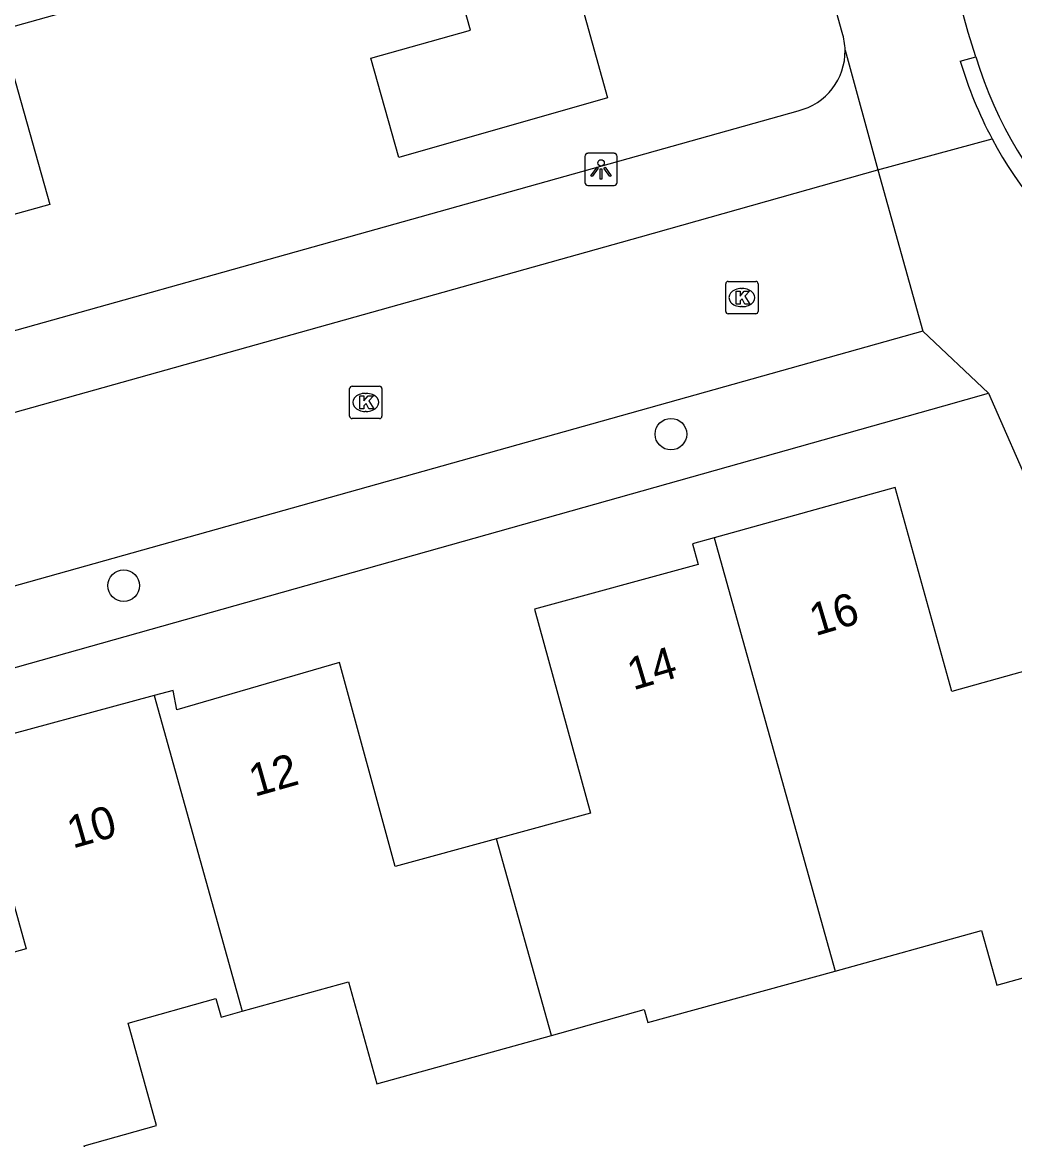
# Model space of a CAD drawing. Extents: x 159628 to 160723, y 388176 to 389416.
# Drawn here: x 160120.05 to 160150.76, y 388377.97 to 388412.56 of the extents above; entities that cross this region are included whole.
import ezdxf

# ---------------------------------------------------------------- set-up
doc = ezdxf.new("R2010")
doc.units = 0
for name, color, linetype in [('IMGEO_Boom', 7, 'Continuous'), ('IMGEO_Kolk', 7, 'Continuous'), ('IMGEO_Lichtpunt', 7, 'Continuous'), ('IMGEO_Pand', 7, 'Continuous'), ('IMGEO_Pand_nummerreeks', 7, 'Continuous'), ('IMGEO_Rijbaan_lokaal_open', 7, 'Continuous'), ('IMGEO_Voetpad_open', 7, 'Continuous')]:
    doc.layers.add(name, color=color, linetype=linetype)

msp = doc.modelspace()

# ---------------------------------------------------------------- linework, layer by layer
at = {"layer": 'IMGEO_Boom'}
for centre in [(160140.122, 388399.811), (160123.188, 388395.123)]:
    msp.add_circle(centre, 0.489, dxfattribs=at)
at = {"layer": 'IMGEO_Kolk'}
for p, q in [((160141.819, 388403.612), (160141.819, 388404.464)), ((160141.894, 388404.538), (160142.746, 388404.538)), ((160142.82, 388404.464), (160142.82, 388403.612)), ((160142.307, 388404.318), (160142.332, 388404.318)), ((160142.33, 388403.758), (160142.305, 388403.758)), ((160142.746, 388403.538), (160141.894, 388403.538)), ((160130.179, 388400.368), (160130.179, 388401.22)), ((160130.254, 388401.294), (160131.106, 388401.294)), ((160130.667, 388401.074), (160130.692, 388401.074)), ((160131.18, 388401.22), (160131.18, 388400.368)), ((160131.106, 388400.294), (160130.254, 388400.294)), ((160130.69, 388400.514), (160130.665, 388400.514))]:
    msp.add_line(p, q, dxfattribs=at)
for points in [[(160141.819, 388403.612), (160141.819, 388404.464)], [(160141.894, 388404.538), (160142.746, 388404.538)], [(160142.82, 388404.464), (160142.82, 388403.612)], [(160142.14, 388404.238), (160142.263, 388404.238), (160142.263, 388404.087), (160142.393, 388404.238), (160142.557, 388404.238), (160142.411, 388404.087), (160142.564, 388403.838), (160142.412, 388403.838), (160142.327, 388404.002), (160142.263, 388403.935), (160142.263, 388403.838), (160142.14, 388403.838), (160142.14, 388404.238)], [(160142.746, 388403.538), (160141.894, 388403.538)], [(160130.179, 388400.368), (160130.179, 388401.22)], [(160130.254, 388401.294), (160131.106, 388401.294)], [(160130.5, 388400.994), (160130.623, 388400.994), (160130.623, 388400.843), (160130.753, 388400.994), (160130.917, 388400.994), (160130.771, 388400.843), (160130.924, 388400.594), (160130.772, 388400.594), (160130.687, 388400.758), (160130.623, 388400.691), (160130.623, 388400.594), (160130.5, 388400.594), (160130.5, 388400.994)], [(160131.18, 388401.22), (160131.18, 388400.368)], [(160131.106, 388400.294), (160130.254, 388400.294)]]:
    msp.add_lwpolyline(points, dxfattribs=at)
for centre, start, end in [((160141.896, 388404.462), 91.552, 178.448), ((160141.896, 388404.462), 91.552, 178.448), ((160142.744, 388404.462), 1.552, 88.448), ((160142.744, 388404.462), 1.552, 88.448), ((160141.896, 388403.614), 181.552, 268.448), ((160141.896, 388403.614), 181.552, 268.448), ((160142.744, 388403.614), 271.552, 358.448), ((160142.744, 388403.614), 271.552, 358.448), ((160130.256, 388401.218), 91.552, 178.448), ((160130.256, 388401.218), 91.552, 178.448), ((160131.104, 388401.218), 1.552, 88.448), ((160131.104, 388401.218), 1.552, 88.448), ((160130.256, 388400.37), 181.552, 268.448), ((160130.256, 388400.37), 181.552, 268.448), ((160131.104, 388400.37), 271.552, 358.448), ((160131.104, 388400.37), 271.552, 358.448)]:
    msp.add_arc(centre, 0.0765, start, end, dxfattribs=at)
for centre, major_axis, ratio, start_param, end_param in [((160142.306, 388404.038), (-0.387, 0.002), 0.722429, 4.712389, 7.853982), ((160142.331, 388404.038), (-0.39, 0.002), 0.717154, 1.570796, 4.712389), ((160130.666, 388400.794), (-0.387, 0.002), 0.722429, 4.712389, 7.853982), ((160130.691, 388400.794), (-0.39, 0.002), 0.717154, 1.570796, 4.712389)]:
    msp.add_ellipse(centre, major_axis=major_axis, ratio=ratio, start_param=start_param, end_param=end_param, dxfattribs=at)
at = {"layer": 'IMGEO_Lichtpunt'}
for p, q in [((160137.462, 388408.409), (160137.462, 388407.602)), ((160137.462, 388408.409), (160137.462, 388407.602)), ((160138.364, 388408.504), (160137.556, 388408.504)), ((160138.364, 388408.504), (160137.556, 388408.504)), ((160138.458, 388407.602), (160138.458, 388408.409)), ((160138.458, 388407.602), (160138.458, 388408.409)), ((160137.556, 388407.508), (160138.364, 388407.508)), ((160137.556, 388407.508), (160138.364, 388407.508))]:
    msp.add_line(p, q, dxfattribs=at)
for points in [[(160137.836, 388408.073), (160137.875, 388408.045), (160137.687, 388407.783), (160137.649, 388407.81), (160137.836, 388408.073)], [(160137.938, 388408.025), (160137.985, 388408.025), (160137.985, 388407.703), (160137.938, 388407.703), (160137.938, 388408.025)], [(160138.048, 388408.045), (160138.086, 388408.072), (160138.273, 388407.81), (160138.234, 388407.782), (160138.048, 388408.045)]]:
    msp.add_lwpolyline(points, dxfattribs=at)
msp.add_circle((160137.961, 388408.207), 0.0994, dxfattribs=at)
for centre, start, end in [((160137.556, 388408.409), 90, 180), ((160137.556, 388408.409), 90, 180), ((160138.364, 388408.409), 0, 90), ((160138.364, 388408.409), 0, 90), ((160137.556, 388407.602), 180, 270), ((160137.556, 388407.602), 180, 270), ((160138.364, 388407.602), 270, 0), ((160138.364, 388407.602), 270, 360)]:
    msp.add_arc(centre, 0.0946, start, end, dxfattribs=at)
at = {"layer": 'IMGEO_Pand'}
for points in [[(160141.063, 388420.45), (160142.68, 388414.678), (160137.333, 388413.181), (160138.161, 388410.225), (160131.7, 388408.378), (160130.835, 388411.448), (160133.924, 388412.32), (160132.322, 388418)], [(160112.657, 388414.061), (160118.362, 388415.66), (160117.498, 388418.739), (160120.567, 388419.598), (160121.024, 388417.966), (160122.373, 388413.151), (160119.389, 388412.314), (160120.898, 388406.925), (160115.113, 388405.312)], [(160145.208, 388383.185), (160149.736, 388384.445), (160150.207, 388382.753), (160153.617, 388383.702), (160153.571, 388386.582), (160153.212, 388387.884), (160151.883, 388392.704), (160148.822, 388391.847), (160147.062, 388398.164), (160141.458, 388396.605)], [(160141.458, 388396.605), (160140.787, 388396.418), (160140.964, 388395.773), (160135.905, 388394.39), (160137.632, 388388.077), (160134.722, 388387.282)], [(160141.458, 388396.605), (160145.208, 388383.185)], [(160134.722, 388387.282), (160131.589, 388386.426), (160129.864, 388392.739), (160124.827, 388391.278), (160124.714, 388391.873), (160124.13, 388391.716)], [(160124.13, 388391.716), (160118.417, 388390.176), (160120.17, 388383.875), (160117.122, 388383.028), (160118.462, 388378.212), (160119.186, 388375.612), (160122.322, 388376.484), (160121.961, 388377.783), (160124.202, 388378.407), (160123.321, 388381.583), (160126.043, 388382.341), (160126.204, 388381.764), (160126.857, 388381.946)], [(160124.13, 388391.716), (160126.857, 388381.946)], [(160136.425, 388381.198), (160134.722, 388387.282)], [(160136.425, 388381.198), (160139.295, 388381.997), (160139.405, 388381.597), (160145.208, 388383.185)], [(160126.857, 388381.946), (160130.14, 388382.859), (160131.021, 388379.695), (160136.425, 388381.198)]]:
    msp.add_lwpolyline(points, dxfattribs=at)
at = {"layer": 'IMGEO_Rijbaan_lokaal_open'}
for points in [[(160149.559, 388411.487), (160149.324, 388412.243), (160149.064, 388413.184)], [(160149.078, 388411.352), (160149.559, 388411.487)], [(160095.449, 388321.154), (160076.62, 388388.378), (160139.18, 388405.917), (160146.522, 388407.997)], [(160146.522, 388407.997), (160147.918, 388403.002)], [(160147.918, 388403.002), (160140.604, 388400.943), (160085.382, 388385.449), (160084.141, 388382.584), (160083.883, 388381.26), (160100.358, 388322.544)]]:
    msp.add_lwpolyline(points, dxfattribs=at)
for centre, radius, start, end in [((160161.608, 388415.1), 13.078, 196.6533, 208.0252), ((160161.64, 388415.116), 12.614, 196.7198, 253.8312), ((160161.639, 388415.115), 13.113, 208.0211, 253.9758)]:
    msp.add_arc(centre, radius, start, end, dxfattribs=at)
at = {"layer": 'IMGEO_Voetpad_open'}
for points in [[(160145.423, 388412.242), (160135.774, 388446.888), (160134.059, 388453.138)], [(160145.513, 388411.698), (160146.522, 388407.997)], [(160075.33, 388405.904), (160079.333, 388391.671), (160144.062, 388409.821)], [(160146.522, 388407.997), (160150.063, 388408.955)], [(160149.951, 388401.077), (160151.369, 388397.86), (160251.805, 388404.253)], [(160147.918, 388403.002), (160149.951, 388401.077)], [(160087.156, 388383.386), (160148.565, 388400.687), (160149.951, 388401.077)]]:
    msp.add_lwpolyline(points, dxfattribs=at)
for centre, radius, start, end in [((160143.639, 388411.667), 1.875, 0.9366, 17.8514), ((160143.617, 388411.664), 1.896, 283.5686, 1.0203)]:
    msp.add_arc(centre, radius, start, end, dxfattribs=at)

# ---------------------------------------------------------------- texts
at = {"layer": 'IMGEO_Pand_nummerreeks'}
for s, rotation, p in [('16', 16.5792, (160144.592, 388393.554)), ('14', 16.5792, (160138.955, 388391.876)), ('12', 15.8939, (160127.235, 388388.58)), ('10', 15.8939, (160121.608, 388386.978))]:
    msp.add_text(s, height=1, rotation=rotation, dxfattribs=at).set_placement(p)

doc.saveas('drawing.dxf')
